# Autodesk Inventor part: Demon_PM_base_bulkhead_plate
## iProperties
Shininess: 64.0
Length Units: 11269
Angle Units: 11279
Time Units: 11290
Mass Units: 11283
Length Display Precision: 3
Angle Display Precision: 2
Compacted: True
Part Number: Demon_PM_base_bulkhead_plate
Document SubType Name: Modeling
Created: 2005-04
Material: Steel, Mild
Designer: John Blackburn
Manufacturer: Standard
Standards Organization: Custom
Density: 0.0
Volumn: 0.0
Area: 0.0
PropertySet Name: Model Information
Control State: 0
Master: False
Checked Out: False
Author: John Blackburn
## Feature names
1. Extrusion1
